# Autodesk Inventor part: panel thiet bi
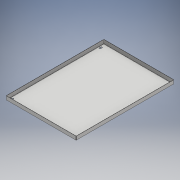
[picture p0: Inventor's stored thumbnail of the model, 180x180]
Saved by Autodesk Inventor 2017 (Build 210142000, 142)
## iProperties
Created: 2022-04
Part Number: panel thiet bi
Material: Generic
Document SubType Name: Sheet Metal
Designer: phat
Density: 1 g/cm^3
Sheet Metal Rule: Default_mm
Appearance: Default
Author: phat
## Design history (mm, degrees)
node "Face1"
  sketch "Sketch1"
    geometry: L1 (-190, 265)-(190, 265); L2 (190, 265)-(190, -265); L3 (190, -265)-(-190, -265); L4 (-190, -265)-(-190, 265); L5 (-190, 265)-(190, -265); L6 (190, 265)-(-190, -265); 1 further point
    constraints: 12 end point, 2 midpoint, 2 parallel, 1 horizontal, 1 perpendicular
    dimensions: "d0" = 380 distance of L2.end L3.end; "d1" = 530 distance of L1.end L2.end
sketch "Sketch2"
  geometry: L1 (-190, 265)-(190, 265) reference; L2 (-190, -265)-(-190, 265) reference; L3 (-178, 240)-(-178, 232); L4 (-182, 240)-(-182, 232); L5 (-174, 232)-(-174, 240); A1 r 4 centre (-178, 240) between (-174, 240) and (-182, 240); A2 r 4 centre (-178, 232) between (-182, 232) and (-174, 232); 2 further points
  constraints: 8 end point, 4 point on circle, 4 tangent, 2 centre point, 1 midpoint, 1 parallel, 1 vertical
  dimensions: "d3" = 25 distance from line of L1 L3.start; "d4" = 12 distance from line of L2 L3.start; "d5" = 8 distance of L3.start L3.end; "d6" = 8 diameter of A2
cut "Cut1" sketch "Sketch2" dims "d7" = 1.2 (= Thickness), "d8" = 0
pattern_linear "Rectangular Pattern1" dims "d11" = 356, "d14" = 480
node "Flange1"
body "Solid1"
face "Plate1" dims "Thickness" = 1.2 (derived)
sketch "Sketch3"
  geometry: L1 through (-190, 0) direction (1, 0); L2 through (0, 10.5) direction (0, 1); L3 (0, 21)-(-380, 21); L4 (-380, 21)-(-380, 0)
  constraints: 6 end point, 1 horizontal, 1 perpendicular, 1 vertical
face "Plate2" dims "d15" = 1.2 (= BendReliefWidth), "d16" = 0.6 (= BendReliefDepth), "d17" = 2.4 (= MinimumRemnant), "d18" = 1.2 (= BendRadius), "d19" = 21, "d20" = 90 deg, "d21" = 1.2 (= BendRadius), "d22" = 4.8 (= CornerReliefSize), "d23" = 1.2 (= GapSize), "d24" = 1.2 (= JacobiRadiusSize), "SeamGap" = 0.01, "Thickness" = 1.2 (derived)
bend "Bend1" dims "d15" = 1.2 (= BendReliefWidth), "d16" = 0.6 (= BendReliefDepth), "d17" = 2.4 (= MinimumRemnant), "d18" = 1.2 (= BendRadius), "d19" = 21, "d20" = 90 deg, "d21" = 1.2 (= BendRadius), "SeamGap" = 0.01, "Thickness" = 1.2 (derived)
feature "Corner1" dims "d19" = 21, "d20" = 90 deg, "d22" = 4.8 (= CornerReliefSize), "d23" = 1.2 (= GapSize), "d24" = 1.2 (= JacobiRadiusSize)
other parameters: "BendRadius" = 1.2 (= Thickness), "BendReliefWidth" = 1.2 (= Thickness), "BendReliefDepth" = 0.6 (= 0.5 x Thickness), "CornerReliefSize" = 4.8 (= 4 x Thickness), "MinimumRemnant" = 2.4 (= 2 x Thickness), "TransitionRadius" = 1.2 (= BendRadius), "JacobiRadiusSize" = 1.2 (= BendRadius), "GapSize" = 1.2 (= Thickness), "d2" = 1.2 (= BendRadius)
